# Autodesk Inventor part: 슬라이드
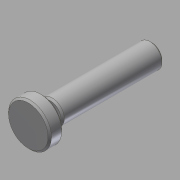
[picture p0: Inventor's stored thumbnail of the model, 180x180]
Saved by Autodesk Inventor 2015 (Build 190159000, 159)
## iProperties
Created: 2015-09
Part Number: 슬라이드
Material: 강철, 연강
Document SubType Name: Modeling
Designer: mduedu
Density: 1 g/cm^3
Appearance: 강철
Author: mduedu
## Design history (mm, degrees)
sketch "스케치1"
  geometry: C1 r 12.5 at (0, 0); 1 further point
  constraints: 1 centre point, 1 coincident
  dimensions: "d0" = 25 diameter of C1
extrude "돌출1" new body sketch "스케치1" distance "d1" = 8; taper "d2" = 0 deg
sketch "스케치2"
  geometry: C1 r 4 at (0, 0); 1 further point
  constraints: 1 centre point, 1 coincident
  dimensions: "d3" = 8 diameter of C1
extrude "돌출2" join sketch "스케치2" distance "d4" = 5; taper "d5" = 0 deg
sketch "스케치3"
  geometry: C1 r 7 at (0, 0); 1 further point
  constraints: 1 centre point, 1 coincident
  dimensions: "d6" = 14 diameter of C1
extrude "돌출3" join sketch "스케치3" distance "d7" = 59; taper "d8" = 0 deg
hole "구멍1" diameter "d11" = 4.134; stored, may be unused: countersink angle "d15" = 90 deg, drill point angle "d17" = 118 deg; dims "d9" = 10, "d10" = 10, "d12" = 9, "d13" = 4, "d14" = 2, "d16" = 12
chamfer "모따기1" distance "d18" = 1; stored, may be unused: second distance "d19" = 2, angle "d20" = 45 deg
node "솔리드1"
